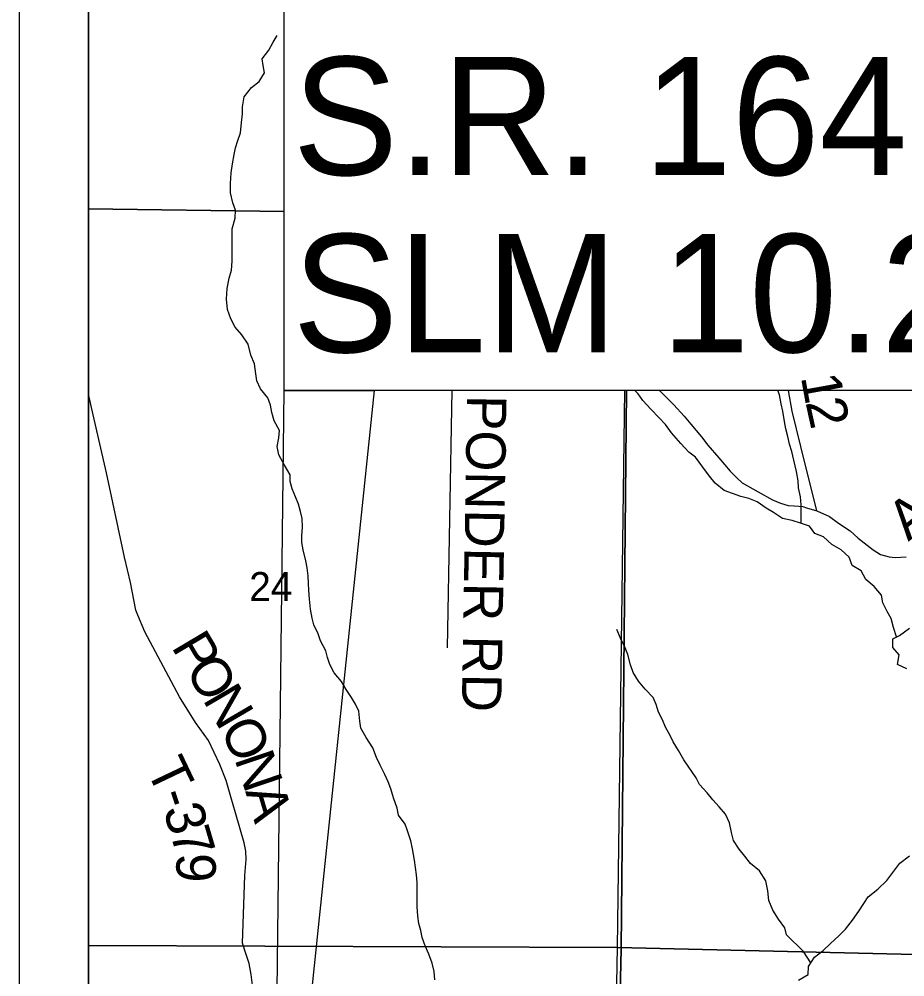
# Model space of a CAD drawing. Extents: x -20.5 to 34, y -66 to 23.9.
# Drawn here: x 2 to 3.275, y 16.397 to 17.775 of the extents above; entities that cross this region are included whole.
import ezdxf

# ---------------------------------------------------------------- set-up
doc = ezdxf.new("R2010")
doc.units = 0
for name, color, linetype in [('Default', 7, 'Continuous'), ('GM_X_County_Text', 7, 'Continuous'), ('GM_X_Minor_Lake', 7, 'Continuous'), ('GM_X_Minor_River_Text', 7, 'Continuous'), ('GM_X_Section_Text', 7, 'Continuous'), ('GM_X_State_Route', 7, 'Continuous'), ('GM_X_Township_Road_Text', 7, 'Continuous'), ('GM_X_Township_Text', 7, 'Continuous'), ('SH_Cut_Line', 7, 'Continuous'), ('SH_Data', 7, 'Continuous'), ('SH_Text', 7, 'Continuous')]:
    doc.layers.add(name, color=color, linetype=linetype)

msp = doc.modelspace()

# ---------------------------------------------------------------- linework, layer by layer
at = {"layer": 'Default'}
for points in [[(2.1, 20.9), (8.9, 20.9), (8.9, 14.1), (2.1, 14.1)], [(2.1, 16.4424), (2.1, 15.425), (2.8417, 15.4083), (2.8609, 16.4392)]]:
    msp.add_lwpolyline(points, close=True, dxfattribs=at)
for points in [[(2.88, 18.0245), (2.8801, 18.0269), (2.8826, 18.5075), (2.8861, 18.9025), (2.8866, 19.0123), (2.1138, 19.0238), (2.1, 19.024), (2.1, 14.4131), (2.1154, 14.4129), (2.8202, 14.4012), (2.823, 14.4012), (2.8374, 14.7884), (2.8447, 15.4785), (2.8665, 16.4374), (2.8739, 17.2409)], [(2.8799, 18.0245), (2.8841, 18.5113), (2.1, 18.5168), (2.1, 17.502), (2.3813, 17.4986)], [(2.3813, 17.4986), (2.1, 17.502), (2.1, 16.4424), (2.8609, 16.4392), (2.8718, 17.2409)], [(2.8739, 17.2409), (2.8665, 16.4374), (2.8447, 15.4785), (2.8374, 14.7884)]]:
    msp.add_lwpolyline(points, dxfattribs=at)
at = {"layer": 'GM_X_County_Text'}
msp.add_line((2.6225, 17.2409), (2.6159, 16.8706), dxfattribs=at)
for points in [[(3.1482, 17.0676), (3.1248, 17.1603), (3.1125, 17.2112), (3.1072, 17.2409)], [(2.3536, 16.2435), (2.3337, 16.4008), (2.3312, 16.4164), (2.3261, 16.4309), (2.3214, 16.4458), (2.325, 16.5432), (2.3266, 16.5662), (2.3261, 16.5778), (2.3239, 16.5898), (2.3112, 16.6333), (2.3047, 16.6562), (2.2977, 16.6798), (2.289, 16.7028), (2.2727, 16.7372), (2.2538, 16.7633), (2.2308, 16.8003), (2.1809, 16.8934), (2.1708, 16.9175), (2.1681, 16.9247), (2.1603, 16.9646), (2.1514, 17.0009), (2.1259, 17.1226), (2.1066, 17.206), (2.1, 17.2355)]]:
    msp.add_lwpolyline(points, dxfattribs=at)
at = {"layer": 'GM_X_Minor_Lake'}
msp.add_lwpolyline([(3.8974, 17.2409), (3.8817, 16.4153), (2.8609, 16.4392), (2.8718, 17.2409)], dxfattribs=at)
msp.add_lwpolyline([(3.8817, 16.4153), (3.8622, 15.401), (2.8417, 15.4083), (2.8609, 16.4392)], close=True, dxfattribs=at)
at = {"layer": 'GM_X_Minor_River_Text'}
for points in [[(2.3636, 17.2093), (2.3619, 17.2199), (2.3579, 17.2305), (2.3475, 17.2432), (2.3423, 17.2548), (2.3407, 17.265), (2.3389, 17.279), (2.3334, 17.2915), (2.3297, 17.3077), (2.3204, 17.3208), (2.3107, 17.332), (2.3045, 17.344), (2.2997, 17.3576), (2.2983, 17.3724), (2.2996, 17.3875), (2.3023, 17.4027), (2.3055, 17.4138), (2.3068, 17.4267), (2.3065, 17.4464), (2.3066, 17.4608), (2.3068, 17.4733), (2.3107, 17.4889), (2.3112, 17.5003), (2.3077, 17.5109), (2.3044, 17.5252), (2.3041, 17.5389), (2.305, 17.554), (2.3071, 17.567), (2.3095, 17.5803), (2.3112, 17.5902), (2.3148, 17.6004), (2.3188, 17.6115), (2.3201, 17.6263), (2.3214, 17.6388), (2.3216, 17.6491), (2.324, 17.6635), (2.3343, 17.677), (2.3455, 17.6855), (2.3533, 17.6978), (2.3512, 17.7083), (2.3499, 17.7182), (2.3595, 17.7305), (2.3658, 17.7419), (2.3713, 17.7515)], [(3.2627, 16.8862), (3.2581, 16.8997), (3.2552, 16.9126), (3.2494, 16.9227), (3.2431, 16.9351), (3.241, 16.9464), (3.2306, 16.9588), (3.2187, 16.9688), (3.2117, 16.9812), (3.199, 16.9889), (3.1943, 17.001), (3.1831, 17.0118), (3.1694, 17.0191), (3.1578, 17.0303), (3.1452, 17.035), (3.1375, 17.0455), (3.1245, 17.0502), (3.1127, 17.0538), (3.0987, 17.0566), (3.0857, 17.0651), (3.075, 17.0717), (3.0623, 17.0806), (3.0501, 17.0853), (3.0387, 17.0885), (3.0265, 17.0925), (3.0147, 17.0972), (3.0017, 17.1076), (2.9935, 17.1177), (2.9839, 17.1304), (2.9734, 17.1447), (2.9638, 17.1521), (2.9522, 17.1648), (2.9387, 17.1801), (2.9302, 17.1917), (2.9213, 17.2014), (2.909, 17.2141), (2.8978, 17.2264), (2.8908, 17.2361), (2.8859, 17.2409)], [(3.1255, 17.0499), (3.1254, 17.0669), (3.1256, 17.0764), (3.1247, 17.0877), (3.1218, 17.1006), (3.1209, 17.1108), (3.1187, 17.1244), (3.1147, 17.1406), (3.1122, 17.1531), (3.1086, 17.1637), (3.1061, 17.1746), (3.1033, 17.1859), (3.1016, 17.1961), (3.0991, 17.2113), (3.0966, 17.2218), (3.0941, 17.2347), (3.092, 17.2409)], [(2.5982, 16.3929), (2.5973, 16.4047), (2.5944, 16.4171), (2.5897, 16.4296), (2.5845, 16.442), (2.5802, 16.454), (2.5781, 16.4639), (2.5753, 16.4741), (2.5736, 16.4846), (2.5726, 16.4983), (2.5728, 16.5089), (2.5726, 16.5203), (2.5728, 16.5328), (2.5718, 16.5438), (2.5705, 16.5544), (2.5688, 16.5649), (2.5659, 16.5812), (2.5638, 16.5929), (2.559, 16.6072), (2.5554, 16.617), (2.5461, 16.6298), (2.5441, 16.64), (2.5389, 16.6547), (2.5349, 16.6679), (2.5309, 16.678), (2.5262, 16.6882), (2.5195, 16.7017), (2.5144, 16.713), (2.5089, 16.7266), (2.4992, 16.7416), (2.4917, 16.7551), (2.4904, 16.7649), (2.4891, 16.7793), (2.4843, 16.7895), (2.4785, 16.7992), (2.4707, 16.8105), (2.4637, 16.8221), (2.4533, 16.8348), (2.447, 16.8464), (2.4438, 16.8566), (2.4414, 16.8664), (2.4339, 16.8807), (2.4304, 16.8905), (2.4241, 16.9037), (2.4216, 16.9135), (2.4195, 16.9263), (2.4178, 16.9407), (2.4168, 16.9536), (2.4166, 16.9631), (2.4161, 16.9744), (2.4147, 16.9858), (2.4127, 16.996), (2.4086, 17.0115), (2.4069, 17.022), (2.4068, 17.0315), (2.408, 17.0444), (2.4075, 17.0565), (2.405, 17.0667), (2.4018, 17.0773), (2.3978, 17.0878), (2.3931, 17.0995), (2.3899, 17.1101), (2.3901, 17.1196), (2.3819, 17.1334), (2.3737, 17.1481), (2.3712, 17.1602), (2.3737, 17.1727), (2.3746, 17.1834), (2.3672, 17.1973), (2.3636, 17.2093)], [(3.1394, 16.4174), (3.129, 16.4339), (3.1044, 16.4577), (3.102, 16.4675), (3.093, 16.4803), (3.0845, 16.493), (3.079, 16.5069), (3.0776, 16.5209), (3.0747, 16.5353), (3.0654, 16.5499), (3.0527, 16.5603), (3.0446, 16.5708), (3.0364, 16.5809), (3.0283, 16.5936), (3.025, 16.605), (3.0222, 16.6186), (3.0166, 16.6314), (3.0074, 16.6418), (2.9981, 16.6519), (2.99, 16.662), (2.9792, 16.6739), (2.9745, 16.6837), (2.9566, 16.7096), (2.9488, 16.7227), (2.941, 16.7355), (2.9363, 16.7452), (2.9309, 16.7554), (2.9254, 16.7678), (2.9203, 16.7779), (2.917, 16.7889), (2.9123, 16.799), (2.9011, 16.811), (2.8915, 16.8226), (2.8837, 16.8353), (2.8797, 16.8462), (2.8761, 16.861), (2.8721, 16.8708), (2.8654, 16.8843), (2.8603, 16.8971)], [(3.2773, 16.8402), (3.2639, 16.8464), (3.2667, 16.8604), (3.2575, 16.8709), (3.2572, 16.8834), (3.267, 16.8885), (3.2816, 16.899)], [(3.1218, 16.3924), (3.1353, 16.4006), (3.1358, 16.412), (3.1447, 16.4254), (3.157, 16.4351), (3.1678, 16.4451), (3.1798, 16.4563), (3.1894, 16.466), (3.1991, 16.4787), (3.2083, 16.4917), (3.2157, 16.5025), (3.222, 16.5124), (3.2358, 16.5233), (3.2488, 16.536), (3.2588, 16.5491), (3.2673, 16.561), (3.2815, 16.5714)]]:
    msp.add_lwpolyline(points, dxfattribs=at)
at = {"layer": 'GM_X_State_Route'}
msp.add_lwpolyline([(2.921, 17.2409), (2.9219, 17.2402), (2.9424, 17.2202), (2.9572, 17.2041), (2.9667, 17.1925), (2.9818, 17.1741), (2.9913, 17.1621), (3.007, 17.1441), (3.0231, 17.1246), (3.0328, 17.1154), (3.0405, 17.1081), (3.0482, 17.1037), (3.0634, 17.095), (3.0841, 17.0837), (3.0958, 17.0785), (3.1067, 17.0754), (3.1152, 17.0748), (3.1221, 17.0746), (3.128, 17.0738), (3.1331, 17.0722), (3.1482, 17.0676), (3.1664, 17.0596), (3.1793, 17.05), (3.1958, 17.0388), (3.2076, 17.0285), (3.2293, 17.0117), (3.2397, 17.005), (3.2522, 17.0017), (3.2607, 17.0004), (3.2766, 17.0016)], dxfattribs=at)
at = {"layer": 'SH_Cut_Line'}
msp.add_lwpolyline([(8.0662, 14.9881), (8.0784, 15.8902), (8.0825, 16.3121), (8.087, 16.6605), (8.0955, 17.3258), (8.2289, 17.3235), (8.271, 17.3227), (8.5216, 17.3182), (8.9, 17.3115), (8.9, 20.9), (2.1, 20.9), (2.1, 14.4131)], dxfattribs=at)
at = {"layer": 'SH_Data'}
for p, q in [((2, 21), (2, 14)), ((2.1, 20.9), (2.1, 14.1))]:
    msp.add_line(p, q, dxfattribs=at)
at = {"layer": 'SH_Text'}
for points in [[(2.3813, 18.0245), (4.5524, 18.0245), (4.5524, 17.2409), (2.3813, 17.2409)], [(2.365, 15.8428), (2.3813, 17.2409), (2.5107, 17.2409)]]:
    msp.add_lwpolyline(points, close=True, dxfattribs=at)

# ---------------------------------------------------------------- texts
at = {"layer": 'GM_X_Section_Text'}
for s, height, rotation, p in [('1', 0.0568, 280.2318, (3.1249, 17.2607)), ('PONDER RD', 0.05682, 269.0249, (2.6447, 17.2346)), ('2', 0.0568, 282.3599, (3.1315, 17.2242)), ('P', 0.0568, 300.7356, (2.2182, 16.8722)), ('O', 0.0568, 300.738, (2.2378, 16.8393)), ('N', 0.0568, 300.3106, (2.2633, 16.7964)), ('O', 0.0568, 296.2515, (2.288, 16.7541)), ('T', 0.0568, 295.4687, (2.182, 16.6963)), ('N', 0.0568, 288.697, (2.3094, 16.7111)), ('-', 0.0568, 288.4831, (2.1996, 16.6597)), ('A', 0.0568, 286.5489, (2.3252, 16.6643)), ('3', 0.0568, 286.5652, (2.2069, 16.638)), ('7', 0.0568, 286.4515, (2.2169, 16.6045)), ('9', 0.0568, 270.0729, (2.2262, 16.5752))]:
    msp.add_text(s, height=height, rotation=rotation, dxfattribs=at).set_placement(p)
at = {"layer": 'GM_X_Township_Road_Text'}
msp.add_text('A', height=0.0568, rotation=39.5476, dxfattribs=at).set_placement((3.2797, 17.023))
at = {"layer": 'GM_X_Township_Text'}
msp.add_text('24', height=0.04186, rotation=0, dxfattribs=at).set_placement((2.3311, 16.9378))
at = {"layer": 'SH_Text'}
for s, p in [('S.R. 164', (2.3937, 17.5509)), ('SLM 10.22', (2.3937, 17.2959))]:
    msp.add_text(s, height=0.17, dxfattribs=at).set_placement(p)

doc.saveas('drawing.dxf')
